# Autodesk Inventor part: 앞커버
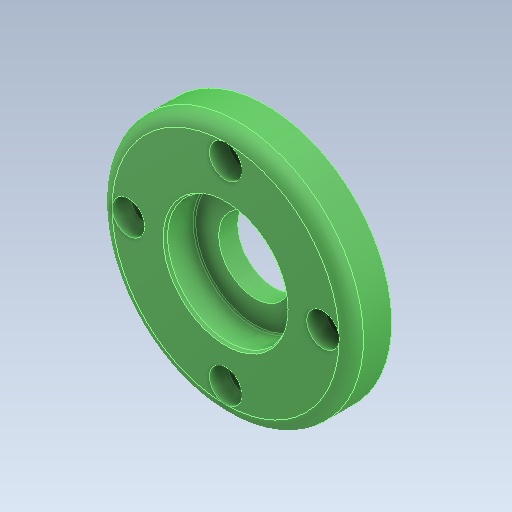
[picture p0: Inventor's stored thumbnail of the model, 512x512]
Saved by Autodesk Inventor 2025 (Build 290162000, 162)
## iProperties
Created: 2024-07
Part Number: 앞커버
Material: 알루미늄 6061
Document SubType Name: Modeling
Designer: 미서니
Density: 2.71 g/cm^3
Appearance: 기본값
Author: jhkim
Sending System: Autodesk Inventor 2025
Preprocessor: ST-DEVELOPER v20
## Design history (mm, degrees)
feature "솔리드1"
node "솔리드2"
